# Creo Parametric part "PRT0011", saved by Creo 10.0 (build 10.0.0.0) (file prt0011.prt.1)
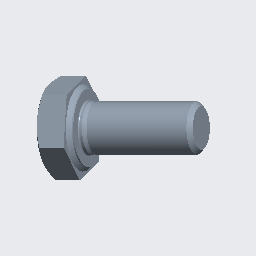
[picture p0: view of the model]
Units: millimeter Newton Second (mmNs); MM, TONNE, SECS

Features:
  1. coordinate system "SCHRAUBEN"
  2. imported feature "Import-ke ID 4"

Surfaces: 14 cone, 11 plane, 6 cylinder, 2 torus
